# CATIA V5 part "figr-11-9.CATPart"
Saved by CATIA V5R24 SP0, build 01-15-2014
Part number: Part1
Bounding box of the stored display mesh (mm): x -50 to 50, y -39.834 to 41.856, z -25 to 25
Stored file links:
  D:\KAVITA\CATIA V5-6R2014 Project_ Kavita\CATIA V5-6R2014_partfiles\Partfiles\c11_catia_v5-6r2014_prt\figr-11-9.CATPart
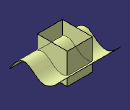
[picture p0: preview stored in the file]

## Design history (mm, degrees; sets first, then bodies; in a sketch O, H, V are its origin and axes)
Set1
  Sketch1 on yz-plane, origin (0, 0, 0), H (0, 1, 0), V (0, 0, 1)
    spline S1 through (-39.8338, -18.0686) (-4.7892, 0) (1.9431, -5.3632) (41.8556, 3.6938)
    point P1 (-4.7892, 0)
    coincidence: P1 H
  Extrude1: Element1 Sketch1, Lim1 50, Lim2 50, Direction yz-plane
  Sketch2 on xy-plane, origin (0, 0, 0), H (1, 0, 0), V (0, 1, 0)
    line L1 (-20.1634, 25.5896) -> (20.7534, 25.5896)
    line L2 (20.7534, 25.5896) -> (20.7534, -23.3463)
    line L3 (20.7534, -23.3463) -> (-20.1634, -23.3463)
    line L4 (-20.1634, -23.3463) -> (-20.1634, 25.5896)
    horizontal: L1 H, L3 H
    vertical: L2 V, L4 V
  Extrude2: Element1 Sketch2, Lim1 25, Lim2 25, Direction xy-plane
  Intersect1: ToIntersect1 Extrude1, ToIntersect2 Extrude2
Body1 (main body)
